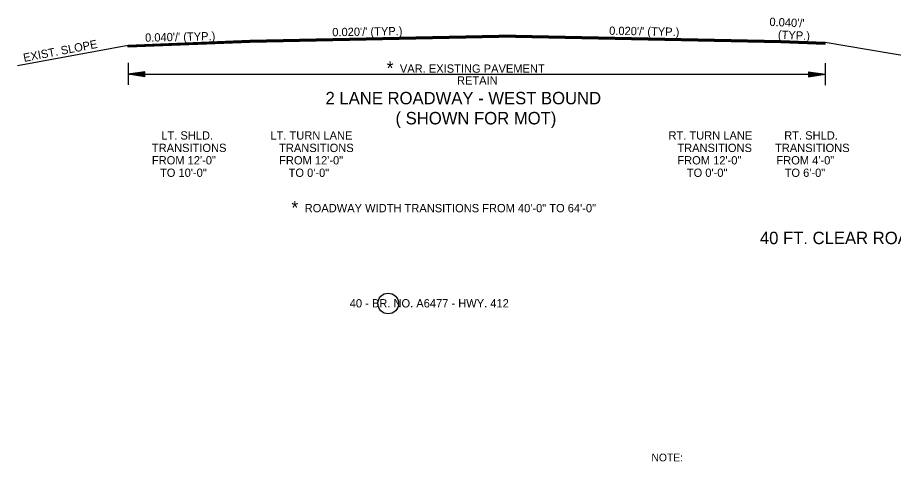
# Model space of a CAD drawing. Extents: x 550980 to 1930787, y -1972975 to 596640.
# Drawn here: x 550982 to 551774, y -1964058 to -1963657 of the extents above; entities that cross this region are included whole.
import ezdxf

# ---------------------------------------------------------------- set-up
doc = ezdxf.new("R2010")
doc.units = 0
for name, color, linetype in [('R_Border', 7, 'Continuous'), ('R_Border Notes', 7, 'Continuous'), ('R_Draft', 7, 'Continuous')]:
    doc.layers.add(name, color=color, linetype=linetype)

msp = doc.modelspace()

# ---------------------------------------------------------------- linework, layer by layer
at = {"layer": 'R_Border'}
msp.add_circle((551317.23, -1963915.15), 9.34, dxfattribs=at)
at = {"layer": 'R_Draft'}
for p, q in [((551432.19, -1963672.52), (551192.19, -1963677.32)), ((551432.19, -1963672.82), (551192.19, -1963677.62)), ((551432.19, -1963673.12), (551192.19, -1963677.92)), ((551432.19, -1963673.42), (551192.19, -1963678.22)), ((551432.19, -1963672.52), (551672.2, -1963677.32)), ((551432.19, -1963672.82), (551672.2, -1963677.62)), ((551432.19, -1963673.12), (551672.2, -1963677.92)), ((551432.19, -1963673.42), (551672.2, -1963678.22)), ((551192.19, -1963677.32), (551082.19, -1963681.72)), ((551192.19, -1963677.62), (551082.19, -1963682.02)), ((551192.19, -1963677.92), (551082.19, -1963682.32)), ((551192.19, -1963678.22), (551082.19, -1963682.62)), ((551192.19, -1963678.52), (551082.19, -1963682.92)), ((551192.19, -1963678.82), (551082.19, -1963683.22)), ((551192.19, -1963678.99), (551082.19, -1963683.39)), ((551432.19, -1963673.72), (551192.19, -1963678.52)), ((551432.19, -1963674.02), (551192.19, -1963678.82)), ((551432.19, -1963674.19), (551192.19, -1963678.99)), ((551432.19, -1963673.72), (551672.2, -1963678.52)), ((551432.19, -1963674.02), (551672.2, -1963678.82)), ((551432.19, -1963674.19), (551672.2, -1963678.99)), ((551672.2, -1963677.32), (551712.2, -1963678.92)), ((551672.2, -1963677.62), (551712.2, -1963679.22)), ((551672.2, -1963677.92), (551712.2, -1963679.52)), ((551672.2, -1963678.22), (551712.2, -1963679.82)), ((551672.2, -1963678.52), (551712.2, -1963680.12)), ((551672.2, -1963678.82), (551712.2, -1963680.42)), ((551672.2, -1963678.99), (551712.21, -1963680.59)), ((551712.2, -1963680.59), (551712.2, -1963678.92)), ((551712.2, -1963678.92), (551895.59, -1963709.48)), ((551082.19, -1963681.72), (550982.12, -1963700.09)), ((551082.19, -1963683.39), (551082.19, -1963681.72)), ((551082.19, -1963697.53), (551082.19, -1963717.53)), ((551712.19, -1963697.78), (551712.19, -1963717.78)), ((551097.19, -1963705.53), (551082.19, -1963707.78)), ((551097.19, -1963710.03), (551082.19, -1963707.78)), ((551082.19, -1963707.78), (551712.19, -1963707.78)), ((551097.19, -1963705.9), (551084.69, -1963707.78)), ((551097.19, -1963709.65), (551084.69, -1963707.78)), ((551097.19, -1963706.28), (551087.27, -1963707.78)), ((551097.19, -1963709.27), (551087.27, -1963707.78)), ((551097.19, -1963706.66), (551089.77, -1963707.78)), ((551097.19, -1963708.89), (551089.77, -1963707.78)), ((551097.19, -1963707.04), (551092.31, -1963707.78)), ((551097.19, -1963708.5), (551092.31, -1963707.78)), ((551097.19, -1963707.42), (551094.82, -1963707.78)), ((551097.19, -1963708.13), (551094.82, -1963707.78)), ((551097.19, -1963710.03), (551097.19, -1963705.53)), ((551697.19, -1963705.53), (551712.19, -1963707.78)), ((551697.19, -1963705.53), (551697.19, -1963710.03)), ((551697.19, -1963705.9), (551709.68, -1963707.78)), ((551697.19, -1963706.28), (551707.1, -1963707.78)), ((551697.19, -1963706.66), (551704.61, -1963707.78)), ((551697.19, -1963707.05), (551702.06, -1963707.78)), ((551697.19, -1963707.42), (551699.56, -1963707.78)), ((551697.19, -1963710.03), (551712.19, -1963707.78)), ((551697.19, -1963708.51), (551702.06, -1963707.78)), ((551697.19, -1963709.27), (551707.1, -1963707.78)), ((551697.19, -1963709.65), (551709.68, -1963707.78)), ((551697.19, -1963708.89), (551704.61, -1963707.78)), ((551697.19, -1963708.13), (551699.56, -1963707.78))]:
    msp.add_line(p, q, dxfattribs=at)

# ---------------------------------------------------------------- texts
at = {"layer": 'R_Border'}
msp.add_text('( SHOWN FOR MOT)', height=11.25, dxfattribs=at).set_placement((551323.83, -1963753.16))
at = {"layer": 'R_Border Notes'}
msp.add_text('NOTE: ', height=7, dxfattribs=at).set_placement((551555.2, -1964057.92))
at = {"layer": 'R_Draft'}
for s, rotation, p in [("  0.040'/'", 357.55203, (551656.14, -1963663.82)), ("0.020'/' (TYP.)", 0.97192, (551266.71, -1963673.51)), ("0.020'/' (TYP.)", 359.02808, (551516.9, -1963672.14)), ("0.040'/' (TYP.)", 1.31838, (551097.54, -1963678.45)), (' (TYP.)', 357.55203, (551666.61, -1963675.53)), ('EXIST. SLOPE', 10.88286, (550988.1, -1963696.72))]:
    msp.add_text(s, height=7.5, rotation=rotation, dxfattribs=at).set_placement(p)
for s, height, p in [('*', 12, (551315.77, -1963708.28)), ('VAR. EXISTING PAVEMENT', 7.5, (551327.77, -1963706.45)), ('RETAIN', 7.5, (551379.38, -1963717.18)), ('2 LANE ROADWAY - WEST BOUND', 11.25, (551260.59, -1963735.02)), ('LT. SHLD.', 7.5, (551112.09, -1963766.89)), ('LT. TURN LANE', 7.5, (551210.74, -1963766.89)), ('RT. TURN LANE', 7.5, (551570.57, -1963766.89)), ('RT. SHLD.', 7.5, (551675.23, -1963766.89)), ('TRANSITIONS', 7.5, (551103.59, -1963778.14)), ('TRANSITIONS', 7.5, (551218.6, -1963778.14)), ('TRANSITIONS', 7.5, (551578.6, -1963778.14)), ('TRANSITIONS', 7.5, (551666.9, -1963778.14)), ('FROM 12\'-0"', 7.5, (551103.61, -1963789.39)), ('FROM 12\'-0"', 7.5, (551218.63, -1963789.39)), ('FROM 12\'-0"', 7.5, (551578.63, -1963789.39)), ('FROM 4\'-0"', 7.5, (551668.17, -1963789.39)), ('TO 10\'-0"', 7.5, (551110.94, -1963800.64)), ('TO 0\'-0"', 7.5, (551227.19, -1963800.64)), ('TO 0\'-0"', 7.5, (551587.19, -1963800.64)), ('TO 6\'-0"', 7.5, (551675.61, -1963800.64)), ('*', 12, (551229.73, -1963834.46)), ('ROADWAY WIDTH TRANSITIONS FROM 40\'-0" TO 64\'-0"', 7.5, (551241.73, -1963832.64)), ('40 FT. CLEAR ROADWAY BRIDGES - POLYMER OVERLAY', 11.25, (551653.24, -1963861.48)), ('      40 - BR. NO. A6477 - HWY. 412', 7.5, (551265.72, -1963918.72))]:
    msp.add_text(s, height=height, dxfattribs=at).set_placement(p)

doc.saveas('drawing.dxf')
